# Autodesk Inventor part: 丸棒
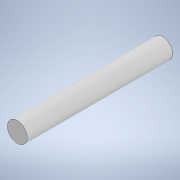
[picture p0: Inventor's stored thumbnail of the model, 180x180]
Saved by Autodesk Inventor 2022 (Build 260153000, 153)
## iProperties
Created: 2024-12
Part Number: 丸棒
Material: 一般
Document SubType Name: Modeling
Designer: jsat7
Density: 1 g/cm^3
Appearance: 既定
Author: jsat7
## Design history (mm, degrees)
sketch "スケッチ1"
  geometry: C1 r 1.5 at (0, 0); 1 further point
  constraints: 1 centre point, 1 coincident
  dimensions: "d0" = 3 diameter of C1
extrude "押し出し1" new body sketch "スケッチ1" distance "d1" = 22; taper "d2" = 0 deg
node "ソリッド1"
